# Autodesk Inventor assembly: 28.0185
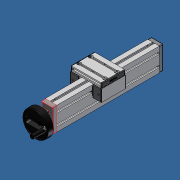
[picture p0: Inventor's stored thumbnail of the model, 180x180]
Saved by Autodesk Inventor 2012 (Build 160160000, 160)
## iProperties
Created: 2007-06
Part Number: 28.0185
Document SubType Name: Assembly
Designer: Andy Moles
Description: ADJUSTING UNIT VEN 45X90H
Author: Andy Moles
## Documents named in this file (20)
- C:\Andys Backup Data\ANDY'S INVENTOR\INVENTOR LIBRARIES\PARTS LIBRARY\READY FOR USE MODULES LG\28.0185 ADJUSTING UNIT VEN 45X90H.iam
- C:\Andys Backup Data\ANDY'S INVENTOR\INVENTOR LIBRARIES\PARTS LIBRARY\READY FOR USE MODULES LG\SUBCOMPONENTS\50.1264 BALL BEARING 10X30X9 6200 2RS DIN 625.ipt
- C:\Andys Backup Data\ANDY'S INVENTOR\INVENTOR LIBRARIES\PARTS LIBRARY\READY FOR USE MODULES LG\SUBCOMPONENTS\28.0201 BEARING PLATE 45X90 IDLER SIDE.ipt
- C:\Andys Backup Data\ANDY'S INVENTOR\INVENTOR LIBRARIES\PARTS LIBRARY\READY FOR USE MODULES LG\SUBCOMPONENTS\28.0200 BEARING PLATE 45X90 HANDWHEEL SIDE.ipt
- C:\Andys Backup Data\ANDY'S INVENTOR\INVENTOR LIBRARIES\PARTS LIBRARY\READY FOR USE MODULES LG\SUBCOMPONENTS\28.0204 HANDWHEEL 100mm.iam
- C:\Andys Backup Data\ANDY'S INVENTOR\INVENTOR LIBRARIES\PARTS LIBRARY\FASTENING ELEMENTS\NUTS\21.1351 M8 SQUARE NUT.ipt
- C:\Andys Backup Data\ANDY'S INVENTOR\INVENTOR LIBRARIES\PARTS LIBRARY\FASTENING ELEMENTS\SCREWS CAP\21.1204 M8X25.ipt
- C:\Andys Backup Data\ANDY'S INVENTOR\INVENTOR LIBRARIES\PARTS LIBRARY\READY FOR USE MODULES LG\SUBCOMPONENTS\28.0214_1 RAIL 45X90 H PROFILE.ipt
- C:\Andys Backup Data\ANDY'S INVENTOR\INVENTOR LIBRARIES\PARTS LIBRARY\FASTENING ELEMENTS\WASHERS\21.1326 DISC SPRING 20.ipt
- C:\Andys Backup Data\ANDY'S INVENTOR\INVENTOR LIBRARIES\PARTS LIBRARY\READY FOR USE MODULES LG\SUBCOMPONENTS\28.0221 ACME SCREW 16X4.ipt
- C:\Andys Backup Data\ANDY'S INVENTOR\INVENTOR LIBRARIES\PARTS LIBRARY\READY FOR USE MODULES LG\SUBCOMPONENTS\28.0222_1 LWN 32X45-45 90X19-NSC.ipt
- 28.0222 SLIDE LWN 32X45-45 90X19.ipt
- C:\Andys Backup Data\ANDY'S INVENTOR\INVENTOR LIBRARIES\PARTS LIBRARY\READY FOR USE MODULES LG\SUBCOMPONENTS\28.0126 SLIDE 45X32.ipt
- C:\Andys Backup Data\ANDY'S INVENTOR\INVENTOR LIBRARIES\PARTS LIBRARY\FASTENING ELEMENTS\SCREWS CAP\21.1235 M5X16.ipt
- C:\Andys Backup Data\ANDY'S INVENTOR\INVENTOR LIBRARIES\PARTS LIBRARY\READY FOR USE MODULES LG\SUBCOMPONENTS\28.0256 Nut slide connector 38.5.ipt
- C:\Andys Backup Data\ANDY'S INVENTOR\INVENTOR LIBRARIES\PARTS LIBRARY\END CAPS\22.1003_1 END CAP 45x32 Z Gray.iam
- C:\Andys Backup Data\ANDY'S INVENTOR\INVENTOR LIBRARIES\PARTS LIBRARY\END CAPS\22.1014_1 END CAP 90X19 GRAY.ipt
- C:\Andys Backup Data\ANDY'S INVENTOR\INVENTOR LIBRARIES\PARTS LIBRARY\COMPONENTS LG\22.1095 SLIDE RAIL LN.iam
- C:\Andys Backup Data\ANDY'S INVENTOR\INVENTOR LIBRARIES\PARTS LIBRARY\READY FOR USE MODULES LG\SUBCOMPONENTS\28.0257 BRONZE NUT 16X4 NOTCHED.ipt
- C:\Andys Backup Data\ANDY'S INVENTOR\INVENTOR LIBRARIES\PARTS LIBRARY\FASTENING ELEMENTS\SCREWS CAP\21.1200 M8X16.ipt
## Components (36 placed, 18 different names)
1. 28.0214_1 RAIL 45X90 H PROFILE:1 — Mate:13, Mate:14, Flush:9, Mate:16, Flush:10, Angle:2, Flush:11, Mate:18, Flush:12, Flush:13, Angle:17, Mate:32, Mate:33
2. 50.1264 10X30X9 6200 2RS DIN 625 BALL BEARING:1 — Insert:9
3. 50.1264 10X30X9 6200 2RS DIN 625 BALL BEARING:2 — Insert:10, Insert:13
4. 28.0201 BEARING PLATE 45X90 IDLER SIDE:1 — Insert:7, Insert:8, Insert:10, Angle:2, Mate:18, Flush:12, Flush:13
5. 28.0200 BEARING PLATE 45X90 HANDWHEEL SIDE:1 — Insert:3, Insert:5, Insert:6, Insert:9, Mate:16, Flush:10, Flush:11, Angle:6, Angle:18
6. 28.0204 HANDWHEEL 100mm:1 [sub-assembly] — Insert:3, Angle:5, Angle:6
7. 21.1204  M8 x 25:1 — Insert:6
8. 21.1204  M8 x 25:2 — Insert:5
9. 21.1204  M8 x 25:3 — Insert:8
10. 21.1204  M8 x 25:4 — Insert:7
11. 21.1326 DISC SPRING 20:1 — Insert:11
12. 21.1326 DISC SPRING 20:2 — Insert:12, Insert:13
13. 28.0221 ACME SCREW 16X4:1 — Insert:11, Insert:12, Angle:5, Mate:31
14. 28.0222\1 SLIDE LWN 32X45-45 90X19:1 — Insert:14, Insert:15, Insert:16, Insert:17, Mate:23, Mate:24, Flush:14, Flush:15, Insert:18, Insert:19, Insert:20, Insert:21, Angle:8, Angle:9, Angle:10, Angle:11, Flush:16, Flush:17, Insert:22, Insert:23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
15. 21.1200 M8 x 16:1 — Insert:15
16. 21.1200 M8 x 16:2 — Insert:14
17. 21.1200 M8 x 16:3 — Insert:17
18. 21.1200 M8 x 16:4 — Insert:16
19. 28.0126 SLIDE 45X32:1 — Mate:24, Flush:16, Flush:17, Insert:25, Insert:28, Angle:14, Angle:15, Mate:27, Mate:28
20. 28.0126 SLIDE 45X32:2 — Mate:23, Flush:14, Flush:15, Insert:26, Insert:27, Angle:13, Angle:16, Mate:29, Mate:30
21. 21.1351 M8 SQUARE NUT:2 — Insert:21, Angle:8
22. 21.1351 M8 SQUARE NUT:3 — Insert:18, Angle:10
23. 21.1351 M8 SQUARE NUT:4 — Insert:19, Angle:9
24. 21.1351 M8 SQUARE NUT:5 — Insert:20, Angle:11
25. 21.1235  M5 x 16:1 — Insert:22
26. 21.1235  M5 x 16:2 — Insert:23
27. 28.0256 Nut slide connector 38.5:1 — Insert:24, Angle:12, Mate:34
28. 22.1003\1 END CAP 45x32 Z Gray:1 [sub-assembly] — Insert:26, Angle:13
29. 22.1003\1 END CAP 45x32 Z Gray:2 [sub-assembly] — Insert:25, Angle:14
30. 22.1003\1 END CAP 45x32 Z Gray:3 [sub-assembly] — Insert:27, Angle:16
31. 22.1003\1 END CAP 45x32 Z Gray:4 [sub-assembly] — Insert:28, Angle:15
32. 22.1014_1 END CAP 90X19 GRAY:1 — Mate:26, Flush:20, Flush:21
33. 22.1014_1 END CAP 90X19 GRAY:2 — Mate:25, Flush:18, Flush:19
34. 22.1095 SLIDE RAIL LN:1 [sub-assembly] — Mate:27, Flush:22, Mate:28
35. 22.1095 SLIDE RAIL LN:2 [sub-assembly] — Mate:29, Flush:23, Mate:30, Mate:32, Mate:33
36. 28.0257 BRONZE NUT 16X4 NOTCHED:1 — Mate:31, Mate:34
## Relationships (70: Insert 25, Mate 16, Flush 15, Angle 14)
- Insert:3: 28.0200 BEARING PLATE 45X90 HANDWHEEL SIDE:1 ↔ 28.0204 HANDWHEEL 100mm:1
- Insert:5: 28.0200 BEARING PLATE 45X90 HANDWHEEL SIDE:1 ↔ 21.1204  M8 x 25:2
- Insert:6: 28.0200 BEARING PLATE 45X90 HANDWHEEL SIDE:1 ↔ 21.1204  M8 x 25:1
- Insert:7: 28.0201 BEARING PLATE 45X90 IDLER SIDE:1 ↔ 21.1204  M8 x 25:4
- Insert:8: 28.0201 BEARING PLATE 45X90 IDLER SIDE:1 ↔ 21.1204  M8 x 25:3
- Insert:9: 50.1264 10X30X9 6200 2RS DIN 625 BALL BEARING:1 ↔ 28.0200 BEARING PLATE 45X90 HANDWHEEL SIDE:1
- Insert:10: 50.1264 10X30X9 6200 2RS DIN 625 BALL BEARING:2 ↔ 28.0201 BEARING PLATE 45X90 IDLER SIDE:1
- Mate:13: 28.0214_1 RAIL 45X90 H PROFILE:1
- Mate:14: 28.0214_1 RAIL 45X90 H PROFILE:1
- Flush:9: 28.0214_1 RAIL 45X90 H PROFILE:1
- Mate:16: 28.0214_1 RAIL 45X90 H PROFILE:1 ↔ 28.0200 BEARING PLATE 45X90 HANDWHEEL SIDE:1
- Flush:10: 28.0214_1 RAIL 45X90 H PROFILE:1 ↔ 28.0200 BEARING PLATE 45X90 HANDWHEEL SIDE:1
- Angle:2: 28.0214_1 RAIL 45X90 H PROFILE:1 ↔ 28.0201 BEARING PLATE 45X90 IDLER SIDE:1
- Flush:11: 28.0214_1 RAIL 45X90 H PROFILE:1 ↔ 28.0200 BEARING PLATE 45X90 HANDWHEEL SIDE:1
- Mate:18: 28.0214_1 RAIL 45X90 H PROFILE:1 ↔ 28.0201 BEARING PLATE 45X90 IDLER SIDE:1
- Flush:12: 28.0214_1 RAIL 45X90 H PROFILE:1 ↔ 28.0201 BEARING PLATE 45X90 IDLER SIDE:1
- Flush:13: 28.0214_1 RAIL 45X90 H PROFILE:1 ↔ 28.0201 BEARING PLATE 45X90 IDLER SIDE:1
- Insert:11: 21.1326 DISC SPRING 20:1 ↔ 28.0221 ACME SCREW 16X4:1
- Insert:12: 21.1326 DISC SPRING 20:2 ↔ 28.0221 ACME SCREW 16X4:1
- Insert:13: 50.1264 10X30X9 6200 2RS DIN 625 BALL BEARING:2 ↔ 21.1326 DISC SPRING 20:2
- Angle:5: 28.0204 HANDWHEEL 100mm:1 ↔ 28.0221 ACME SCREW 16X4:1
- Angle:6: 28.0200 BEARING PLATE 45X90 HANDWHEEL SIDE:1 ↔ 28.0204 HANDWHEEL 100mm:1
- Insert:14: 28.0222\1 SLIDE LWN 32X45-45 90X19:1 ↔ 21.1200 M8 x 16:2
- Insert:15: 28.0222\1 SLIDE LWN 32X45-45 90X19:1 ↔ 21.1200 M8 x 16:1
- Insert:16: 28.0222\1 SLIDE LWN 32X45-45 90X19:1 ↔ 21.1200 M8 x 16:4
- Insert:17: 28.0222\1 SLIDE LWN 32X45-45 90X19:1 ↔ 21.1200 M8 x 16:3
- Mate:23: 28.0222\1 SLIDE LWN 32X45-45 90X19:1 ↔ 28.0126 SLIDE 45X32:2
- Mate:24: 28.0222\1 SLIDE LWN 32X45-45 90X19:1 ↔ 28.0126 SLIDE 45X32:1
- Flush:14: 28.0222\1 SLIDE LWN 32X45-45 90X19:1 ↔ 28.0126 SLIDE 45X32:2
- Flush:15: 28.0222\1 SLIDE LWN 32X45-45 90X19:1 ↔ 28.0126 SLIDE 45X32:2
- Insert:18: 28.0222\1 SLIDE LWN 32X45-45 90X19:1 ↔ 21.1351 M8 SQUARE NUT:3
- Insert:19: 28.0222\1 SLIDE LWN 32X45-45 90X19:1 ↔ 21.1351 M8 SQUARE NUT:4
- Insert:20: 28.0222\1 SLIDE LWN 32X45-45 90X19:1 ↔ 21.1351 M8 SQUARE NUT:5
- Insert:21: 28.0222\1 SLIDE LWN 32X45-45 90X19:1 ↔ 21.1351 M8 SQUARE NUT:2
- Angle:8: 28.0222\1 SLIDE LWN 32X45-45 90X19:1 ↔ 21.1351 M8 SQUARE NUT:2
- Angle:9: 28.0222\1 SLIDE LWN 32X45-45 90X19:1 ↔ 21.1351 M8 SQUARE NUT:4
- Angle:10: 28.0222\1 SLIDE LWN 32X45-45 90X19:1 ↔ 21.1351 M8 SQUARE NUT:3
- Angle:11: 28.0222\1 SLIDE LWN 32X45-45 90X19:1 ↔ 21.1351 M8 SQUARE NUT:5
- Flush:16: 28.0222\1 SLIDE LWN 32X45-45 90X19:1 ↔ 28.0126 SLIDE 45X32:1
- Flush:17: 28.0222\1 SLIDE LWN 32X45-45 90X19:1 ↔ 28.0126 SLIDE 45X32:1
- Insert:22: 28.0222\1 SLIDE LWN 32X45-45 90X19:1 ↔ 21.1235  M5 x 16:1
- Insert:23: 28.0222\1 SLIDE LWN 32X45-45 90X19:1 ↔ 21.1235  M5 x 16:2
- Insert:24: 28.0222\1 SLIDE LWN 32X45-45 90X19:1 ↔ 28.0256 Nut slide connector 38.5:1
- Angle:12: 28.0222\1 SLIDE LWN 32X45-45 90X19:1 ↔ 28.0256 Nut slide connector 38.5:1
- Insert:25: 28.0126 SLIDE 45X32:1 ↔ 22.1003\1 END CAP 45x32 Z Gray:2
- Insert:26: 28.0126 SLIDE 45X32:2 ↔ 22.1003\1 END CAP 45x32 Z Gray:1
- Insert:27: 28.0126 SLIDE 45X32:2 ↔ 22.1003\1 END CAP 45x32 Z Gray:3
- Insert:28: 28.0126 SLIDE 45X32:1 ↔ 22.1003\1 END CAP 45x32 Z Gray:4
- Angle:13: 28.0126 SLIDE 45X32:2 ↔ 22.1003\1 END CAP 45x32 Z Gray:1
- Angle:14: 28.0126 SLIDE 45X32:1 ↔ 22.1003\1 END CAP 45x32 Z Gray:2
- Angle:15: 28.0126 SLIDE 45X32:1 ↔ 22.1003\1 END CAP 45x32 Z Gray:4
- Angle:16: 28.0126 SLIDE 45X32:2 ↔ 22.1003\1 END CAP 45x32 Z Gray:3
- Mate:25: 28.0222\1 SLIDE LWN 32X45-45 90X19:1 ↔ 22.1014_1 END CAP 90X19 GRAY:2
- Flush:18: 28.0222\1 SLIDE LWN 32X45-45 90X19:1 ↔ 22.1014_1 END CAP 90X19 GRAY:2
- Flush:19: 28.0222\1 SLIDE LWN 32X45-45 90X19:1 ↔ 22.1014_1 END CAP 90X19 GRAY:2
- Mate:26: 28.0222\1 SLIDE LWN 32X45-45 90X19:1 ↔ 22.1014_1 END CAP 90X19 GRAY:1
- Flush:20: 28.0222\1 SLIDE LWN 32X45-45 90X19:1 ↔ 22.1014_1 END CAP 90X19 GRAY:1
- Flush:21: 28.0222\1 SLIDE LWN 32X45-45 90X19:1 ↔ 22.1014_1 END CAP 90X19 GRAY:1
- Mate:27: 28.0126 SLIDE 45X32:1 ↔ 22.1095 SLIDE RAIL LN:1
- Flush:22: 28.0222\1 SLIDE LWN 32X45-45 90X19:1 ↔ 22.1095 SLIDE RAIL LN:1
- Mate:28: 28.0126 SLIDE 45X32:1 ↔ 22.1095 SLIDE RAIL LN:1
- Mate:29: 28.0126 SLIDE 45X32:2 ↔ 22.1095 SLIDE RAIL LN:2
- Flush:23: 28.0222\1 SLIDE LWN 32X45-45 90X19:1 ↔ 22.1095 SLIDE RAIL LN:2
- Mate:30: 28.0126 SLIDE 45X32:2 ↔ 22.1095 SLIDE RAIL LN:2
- Mate:31: 28.0221 ACME SCREW 16X4:1 ↔ 28.0257 BRONZE NUT 16X4 NOTCHED:1
- Angle:17: 28.0214_1 RAIL 45X90 H PROFILE:1 ↔ 28.0222\1 SLIDE LWN 32X45-45 90X19:1
- Angle:18: 28.0200 BEARING PLATE 45X90 HANDWHEEL SIDE:1 ↔ 28.0222\1 SLIDE LWN 32X45-45 90X19:1
- Mate:32: 28.0214_1 RAIL 45X90 H PROFILE:1 ↔ 22.1095 SLIDE RAIL LN:2
- Mate:33: 28.0214_1 RAIL 45X90 H PROFILE:1 ↔ 22.1095 SLIDE RAIL LN:2
- Mate:34: 28.0256 Nut slide connector 38.5:1 ↔ 28.0257 BRONZE NUT 16X4 NOTCHED:1
